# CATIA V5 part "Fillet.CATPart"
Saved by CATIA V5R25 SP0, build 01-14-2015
Part number: Part1
Bounding box of the stored display mesh (mm): x -37.5 to 37.5, y -94 to 94, z -94 to 94
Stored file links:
  E:\cadcim\GSD_cat_v5-6r2014\Part_files\Fillet.CATPart
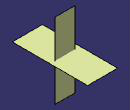
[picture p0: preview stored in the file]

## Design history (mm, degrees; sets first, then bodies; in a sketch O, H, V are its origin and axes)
Body1 (main body)
  Sketch1 on xy-plane, origin (0, 0, 0), H (1, 0, 0), V (0, 1, 0)
    line L1 (-25, 0) -> (25, 0)
    point P1 (-25, 0)
    point P2 (25, 0)
    length L1 = 50
    coincidence: P1 H
    horizontal: L1 H
    symmetry: P1 P2 V
  Sketch2 on zx-plane, origin (0, 0, 0), H (-1, 0, 0), V (0, 0, 1)
    line L1 (-37.5, 0) -> (37.5, 0)
    point P1 (-37.5, 0)
    point P2 (37.5, 0)
    length L1 = 75
    coincidence: P1 H
    horizontal: L1 H
    symmetry: P2 P1 V
  Extrude1: Lim1 94, Lim2 94, Element1 Sketch2
  Extrude2: Lim1 94, Lim2 94, Element1 Sketch1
